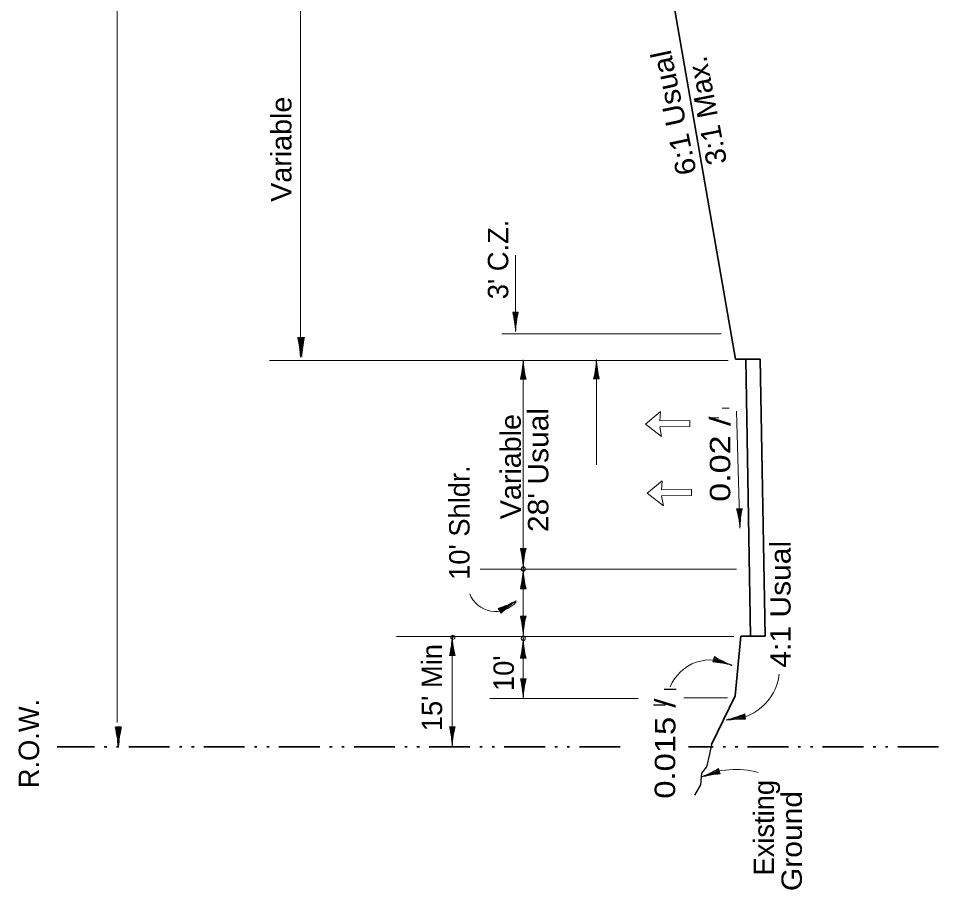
# Model space of a CAD drawing. Extents: x 2363427 to 2368559, y 6957299 to 6980140.
# Drawn here: x 2364644 to 2365275, y 6960219 to 6960816 of the extents above; entities that cross this region are included whole.
import ezdxf
from ezdxf.enums import TextEntityAlignment as Align

# ---------------------------------------------------------------- set-up
doc = ezdxf.new("R2010")
doc.units = 0
doc.header["$LTSCALE"] = 5.6
doc.header["$PDMODE"] = 32
doc.header["$PDSIZE"] = 2.8
doc.linetypes.add('DASH_DOUBLE_DOT', pattern=[9.2, 5, -1.2, 0.3, -1.2, 0.3, -1.2])
doc.linetypes.add('MEDIUM_DASHED', pattern=[4.5, 3, -1.5])
for name, color, linetype, lineweight in [('1', 7, 'Continuous', 13), ('3', 7, 'Continuous', 35), ('4', 7, 'Continuous', 13), ('40', 7, 'Continuous', 35), ('48', 7, 'Continuous', 25), ('8', 7, 'Continuous', 13)]:
    doc.layers.add(name, color=color, linetype=linetype, lineweight=lineweight)

msp = doc.modelspace()

# ---------------------------------------------------------------- linework, layer by layer
at = {"layer": '1'}
for p, q in [((2364983.119, 6960614.672), (2364986.949, 6960614.672)), ((2364983.119, 6960614.672), (2364986.949, 6960614.672)), ((2364983.469, 6960614.672), (2364983.469, 6960613.088)), ((2364983.469, 6960614.672), (2364983.469, 6960613.088)), ((2364983.969, 6960614.672), (2364983.969, 6960610.396)), ((2364983.969, 6960614.672), (2364983.969, 6960610.396)), ((2364984.469, 6960614.672), (2364984.469, 6960607.322)), ((2364984.469, 6960614.672), (2364984.469, 6960607.322)), ((2364984.969, 6960614.672), (2364984.969, 6960602.108)), ((2364984.969, 6960614.672), (2364984.969, 6960602.108)), ((2364985.469, 6960614.672), (2364985.469, 6960606.063)), ((2364985.469, 6960614.672), (2364985.469, 6960606.063)), ((2364985.969, 6960614.672), (2364985.969, 6960609.81)), ((2364985.969, 6960614.672), (2364985.969, 6960609.81)), ((2364986.469, 6960614.672), (2364986.469, 6960612.291)), ((2364986.469, 6960614.672), (2364986.469, 6960612.291))]:
    msp.add_line(p, q, dxfattribs=at)
at = {"layer": '1', "linetype": 'MEDIUM_DASHED', "lineweight": 25}
msp.add_lwpolyline([(2365119.393, 6960318.068), (2365118.041, 6960311.566), (2365116.013, 6960302.896), (2365112.633, 6960298.562), (2365111.957, 6960290.614), (2365107.901, 6960283.39)], dxfattribs=at)
at = {"layer": '1'}
for centre, start, end in [((2364912.912, 6960597.779), 2.84356, 13.52961), ((2364912.912, 6960597.779), 2.84356, 13.52961), ((2365057.159, 6960597.779), 166.47039, 177.15644), ((2365057.159, 6960597.779), 166.47039, 177.15644)]:
    msp.add_arc(centre, 72.212, start, end, dxfattribs=at)
at = {"layer": '3'}
for p, q in [((2365072.809, 6960945.418), (2365135.901, 6960582.428)), ((2365152.924, 6960582.429), (2365135.901, 6960582.428)), ((2365146.244, 6960392.394), (2365142.923, 6960582.429)), ((2365156.242, 6960392.503), (2365152.922, 6960582.516)), ((2365139.652, 6960392.365), (2365156.244, 6960392.437)), ((2365139.652, 6960392.365), (2365135.796, 6960351.6)), ((2365135.795, 6960351.601), (2365119.393, 6960318.069))]:
    msp.add_line(p, q, dxfattribs=at)
at = {"layer": '3', "linetype": 'DASH_DOUBLE_DOT'}
for p, q in [((2365056.852, 6960316.668), (2364670.615, 6960316.668)), ((2365275.227, 6960316.668), (2365103.646, 6960316.668))]:
    msp.add_line(p, q, dxfattribs=at)
at = {"layer": '4'}
for p, q in [((2364711.737, 6960333.27), (2364711.737, 6961383.778)), ((2364837.569, 6960593.58), (2364837.569, 6961228.746)), ((2364985.035, 6960601.361), (2364985.035, 6960653.723)), ((2364835.613, 6960597.226), (2364839.443, 6960597.226)), ((2364835.963, 6960597.226), (2364835.963, 6960595.64)), ((2364836.463, 6960597.226), (2364836.463, 6960592.949)), ((2364836.485, 6960597.226), (2364840.315, 6960597.226)), ((2364836.835, 6960597.226), (2364836.835, 6960595.64)), ((2364836.963, 6960597.226), (2364836.963, 6960589.876)), ((2364837.335, 6960597.226), (2364837.335, 6960592.949)), ((2364837.463, 6960597.226), (2364837.463, 6960584.662)), ((2364837.835, 6960597.226), (2364837.835, 6960589.876)), ((2364837.963, 6960597.226), (2364837.963, 6960588.616)), ((2364838.335, 6960597.226), (2364838.335, 6960584.662)), ((2364838.463, 6960597.226), (2364838.463, 6960592.364)), ((2364838.835, 6960597.226), (2364838.835, 6960588.616)), ((2364838.963, 6960597.226), (2364838.963, 6960594.844)), ((2364839.335, 6960597.226), (2364839.335, 6960592.364)), ((2364839.835, 6960597.226), (2364839.835, 6960594.844)), ((2365126.127, 6960599.72), (2364975.733, 6960599.72)), ((2364990.33, 6960582.06), (2364990.33, 6960349.827)), ((2365040.53, 6960582.3), (2365040.53, 6960510.039)), ((2365130.939, 6960581.552), (2364816.365, 6960581.552)), ((2364989.894, 6960568.748), (2364989.894, 6960577.358)), ((2364989.894, 6960568.748), (2364989.894, 6960577.358)), ((2364990.394, 6960568.748), (2364990.394, 6960581.312)), ((2364990.394, 6960568.748), (2364990.394, 6960581.312)), ((2364990.894, 6960568.748), (2364990.894, 6960576.098)), ((2364990.894, 6960568.748), (2364990.894, 6960576.098)), ((2365039.966, 6960568.989), (2365039.966, 6960576.339)), ((2365039.966, 6960568.989), (2365039.966, 6960576.339)), ((2365040.466, 6960568.989), (2365040.466, 6960581.553)), ((2365040.466, 6960568.989), (2365040.466, 6960581.553)), ((2365040.966, 6960568.989), (2365040.966, 6960577.598)), ((2365040.966, 6960568.989), (2365040.966, 6960577.598)), ((2364988.894, 6960568.748), (2364988.894, 6960571.13)), ((2364988.894, 6960568.748), (2364988.894, 6960571.13)), ((2364989.394, 6960568.748), (2364989.394, 6960573.61)), ((2364989.394, 6960568.748), (2364989.394, 6960573.61)), ((2364991.394, 6960568.748), (2364991.394, 6960573.025)), ((2364991.394, 6960568.748), (2364991.394, 6960573.025)), ((2364991.894, 6960568.748), (2364991.894, 6960570.334)), ((2364991.894, 6960568.748), (2364991.894, 6960570.334)), ((2365038.966, 6960568.989), (2365038.966, 6960570.573)), ((2365038.966, 6960568.989), (2365038.966, 6960570.573)), ((2365039.466, 6960568.989), (2365039.466, 6960573.265)), ((2365039.466, 6960568.989), (2365039.466, 6960573.265)), ((2365041.466, 6960568.989), (2365041.466, 6960573.851)), ((2365041.466, 6960568.989), (2365041.466, 6960573.851)), ((2365041.966, 6960568.989), (2365041.966, 6960571.37)), ((2365041.966, 6960568.989), (2365041.966, 6960571.37)), ((2364992.244, 6960568.748), (2364988.414, 6960568.748)), ((2364992.244, 6960568.748), (2364988.414, 6960568.748)), ((2365038.616, 6960568.989), (2365042.446, 6960568.989)), ((2365038.616, 6960568.989), (2365042.446, 6960568.989)), ((2365136.716, 6960546.874), (2365138.992, 6960466.62)), ((2365140.528, 6960479.981), (2365136.7, 6960479.872)), ((2365137.18, 6960479.886), (2365137.248, 6960477.506)), ((2365137.68, 6960479.9), (2365137.818, 6960475.04)), ((2365138.18, 6960479.914), (2365138.424, 6960471.308)), ((2365138.679, 6960479.928), (2365139.036, 6960467.37)), ((2365139.179, 6960479.942), (2365139.388, 6960472.596)), ((2365139.679, 6960479.957), (2365139.8, 6960475.682)), ((2365140.178, 6960479.971), (2365140.224, 6960478.386)), ((2364988.414, 6960452.662), (2364992.244, 6960452.662)), ((2364988.414, 6960452.662), (2364992.244, 6960452.662)), ((2364988.764, 6960452.662), (2364988.764, 6960451.078)), ((2364988.764, 6960452.662), (2364988.764, 6960451.078)), ((2364989.264, 6960452.662), (2364989.264, 6960448.386)), ((2364989.264, 6960452.662), (2364989.264, 6960448.386)), ((2364989.764, 6960452.662), (2364989.764, 6960445.312)), ((2364989.764, 6960452.662), (2364989.764, 6960445.312)), ((2364990.264, 6960452.662), (2364990.264, 6960440.098)), ((2364990.264, 6960452.662), (2364990.264, 6960440.098)), ((2364990.764, 6960452.662), (2364990.764, 6960444.053)), ((2364990.764, 6960452.662), (2364990.764, 6960444.053)), ((2364991.264, 6960452.662), (2364991.264, 6960447.8)), ((2364991.264, 6960452.662), (2364991.264, 6960447.8)), ((2364991.764, 6960452.662), (2364991.764, 6960450.281)), ((2364991.764, 6960452.662), (2364991.764, 6960450.281)), ((2365136.677, 6960438.365), (2364960.809, 6960438.365)), ((2364990.394, 6960425.013), (2364990.394, 6960437.577)), ((2364990.394, 6960425.013), (2364990.394, 6960437.577)), ((2364989.894, 6960425.013), (2364989.894, 6960433.623)), ((2364989.894, 6960425.013), (2364989.894, 6960433.623)), ((2364990.894, 6960425.013), (2364990.894, 6960432.363)), ((2364990.894, 6960425.013), (2364990.894, 6960432.363)), ((2364992.244, 6960425.013), (2364988.414, 6960425.013)), ((2364992.244, 6960425.013), (2364988.414, 6960425.013)), ((2364988.894, 6960425.013), (2364988.894, 6960427.395)), ((2364988.894, 6960425.013), (2364988.894, 6960427.395)), ((2364989.394, 6960425.013), (2364989.394, 6960429.875)), ((2364989.394, 6960425.013), (2364989.394, 6960429.875)), ((2364991.394, 6960425.013), (2364991.394, 6960429.29)), ((2364991.394, 6960425.013), (2364991.394, 6960429.29)), ((2364991.894, 6960425.013), (2364991.894, 6960426.599)), ((2364991.894, 6960425.013), (2364991.894, 6960426.599)), ((2364975.192, 6960408.208), (2364973.204, 6960411.482)), ((2364973.454, 6960411.071), (2364975.489, 6960412.307)), ((2364973.713, 6960410.645), (2364977.869, 6960413.167)), ((2364973.972, 6960410.217), (2364981.332, 6960414.685)), ((2364974.232, 6960409.789), (2364984.972, 6960416.309)), ((2364974.491, 6960409.362), (2364980.774, 6960413.176)), ((2364974.75, 6960408.935), (2364978.406, 6960411.153)), ((2364975.01, 6960408.507), (2364976.365, 6960409.33)), ((2364988.414, 6960406.184), (2364992.244, 6960406.184)), ((2364988.414, 6960406.184), (2364992.244, 6960406.184)), ((2364988.764, 6960406.184), (2364988.764, 6960404.6)), ((2364988.764, 6960406.184), (2364988.764, 6960404.6)), ((2364989.264, 6960406.184), (2364989.264, 6960401.908)), ((2364989.264, 6960406.184), (2364989.264, 6960401.908)), ((2364989.764, 6960406.184), (2364989.764, 6960398.834)), ((2364989.764, 6960406.184), (2364989.764, 6960398.834)), ((2364990.264, 6960406.184), (2364990.264, 6960393.62)), ((2364990.264, 6960406.184), (2364990.264, 6960393.62)), ((2364990.764, 6960406.184), (2364990.764, 6960397.575)), ((2364990.764, 6960406.184), (2364990.764, 6960397.575)), ((2364991.264, 6960406.184), (2364991.264, 6960401.322)), ((2364991.264, 6960406.184), (2364991.264, 6960401.322)), ((2364991.764, 6960406.184), (2364991.764, 6960403.803)), ((2364991.764, 6960406.184), (2364991.764, 6960403.803)), ((2364941.663, 6960392.504), (2364941.663, 6960316.968)), ((2365134.747, 6960392.301), (2364903.418, 6960392.301)), ((2364941.099, 6960379.192), (2364941.099, 6960386.542)), ((2364941.099, 6960379.192), (2364941.099, 6960386.542)), ((2364941.599, 6960379.192), (2364941.599, 6960391.756)), ((2364941.599, 6960379.192), (2364941.599, 6960391.756)), ((2364942.099, 6960379.192), (2364942.099, 6960387.802)), ((2364942.099, 6960379.192), (2364942.099, 6960387.802)), ((2364990.394, 6960377.417), (2364990.394, 6960389.981)), ((2364990.394, 6960377.417), (2364990.394, 6960389.981)), ((2364940.099, 6960379.192), (2364940.099, 6960380.777)), ((2364940.099, 6960379.192), (2364940.099, 6960380.777)), ((2364940.599, 6960379.192), (2364940.599, 6960383.468)), ((2364940.599, 6960379.192), (2364940.599, 6960383.468)), ((2364942.599, 6960379.192), (2364942.599, 6960384.054)), ((2364942.599, 6960379.192), (2364942.599, 6960384.054)), ((2364943.099, 6960379.192), (2364943.099, 6960381.574)), ((2364943.099, 6960379.192), (2364943.099, 6960381.574)), ((2364988.894, 6960377.417), (2364988.894, 6960379.799)), ((2364988.894, 6960377.417), (2364988.894, 6960379.799)), ((2364989.394, 6960377.417), (2364989.394, 6960382.279)), ((2364989.394, 6960377.417), (2364989.394, 6960382.279)), ((2364989.894, 6960377.417), (2364989.894, 6960386.027)), ((2364989.894, 6960377.417), (2364989.894, 6960386.027)), ((2364990.894, 6960377.417), (2364990.894, 6960384.767)), ((2364990.894, 6960377.417), (2364990.894, 6960384.767)), ((2364991.394, 6960377.417), (2364991.394, 6960381.694)), ((2364991.394, 6960377.417), (2364991.394, 6960381.694)), ((2364939.749, 6960379.192), (2364943.579, 6960379.192)), ((2364939.749, 6960379.192), (2364943.579, 6960379.192)), ((2364992.244, 6960377.417), (2364988.414, 6960377.417)), ((2364992.244, 6960377.417), (2364988.414, 6960377.417)), ((2364991.894, 6960377.417), (2364991.894, 6960379.003)), ((2364991.894, 6960377.417), (2364991.894, 6960379.003)), ((2365120.273, 6960374.788), (2365121.438, 6960378.437)), ((2365120.38, 6960375.121), (2365121.89, 6960374.639)), ((2365120.532, 6960375.598), (2365124.606, 6960374.297)), ((2365120.684, 6960376.074), (2365127.685, 6960373.837)), ((2365120.836, 6960376.551), (2365132.804, 6960372.727)), ((2365120.988, 6960377.027), (2365129.19, 6960374.407)), ((2365121.14, 6960377.503), (2365125.772, 6960376.023)), ((2365121.292, 6960377.979), (2365123.561, 6960377.255)), ((2364988.435, 6960363.224), (2364992.265, 6960363.224)), ((2364988.435, 6960363.224), (2364992.265, 6960363.224)), ((2364988.785, 6960363.224), (2364988.785, 6960361.64)), ((2364988.785, 6960363.224), (2364988.785, 6960361.64)), ((2364989.285, 6960363.224), (2364989.285, 6960358.948)), ((2364989.285, 6960363.224), (2364989.285, 6960358.948)), ((2364989.785, 6960363.224), (2364989.785, 6960355.874)), ((2364989.785, 6960363.224), (2364989.785, 6960355.874)), ((2364990.285, 6960363.224), (2364990.285, 6960350.66)), ((2364990.285, 6960363.224), (2364990.285, 6960350.66)), ((2364990.785, 6960363.224), (2364990.785, 6960354.615)), ((2364990.785, 6960363.224), (2364990.785, 6960354.615)), ((2364991.285, 6960363.224), (2364991.285, 6960358.362)), ((2364991.285, 6960363.224), (2364991.285, 6960358.362)), ((2364991.785, 6960363.224), (2364991.785, 6960360.843)), ((2364991.785, 6960363.224), (2364991.785, 6960360.843)), ((2365069.268, 6960349.827), (2364967.392, 6960349.827)), ((2365130.5, 6960350.216), (2365100.425, 6960350.216)), ((2365142.573, 6960337.281), (2365130.197, 6960335.116)), ((2365142.487, 6960337.775), (2365134.007, 6960336.291)), ((2365142.66, 6960336.789), (2365135.419, 6960335.522)), ((2365142.401, 6960338.267), (2365137.611, 6960337.429)), ((2365142.746, 6960336.297), (2365138.533, 6960335.559)), ((2365142.315, 6960338.759), (2365139.969, 6960338.349)), ((2365142.832, 6960335.805), (2365141.271, 6960335.531)), ((2365142.893, 6960335.46), (2365142.233, 6960339.232)), ((2364943.579, 6960330.28), (2364939.749, 6960330.28)), ((2364943.579, 6960330.28), (2364939.749, 6960330.28)), ((2364940.229, 6960330.28), (2364940.229, 6960327.898)), ((2364940.229, 6960330.28), (2364940.229, 6960327.898)), ((2364940.729, 6960330.28), (2364940.729, 6960325.418)), ((2364940.729, 6960330.28), (2364940.729, 6960325.418)), ((2364941.229, 6960330.28), (2364941.229, 6960321.67)), ((2364941.229, 6960330.28), (2364941.229, 6960321.67)), ((2364941.729, 6960330.28), (2364941.729, 6960317.716)), ((2364941.729, 6960330.28), (2364941.729, 6960317.716)), ((2364942.229, 6960330.28), (2364942.229, 6960322.93)), ((2364942.229, 6960330.28), (2364942.229, 6960322.93)), ((2364942.729, 6960330.28), (2364942.729, 6960326.004)), ((2364942.729, 6960330.28), (2364942.729, 6960326.004)), ((2364943.229, 6960330.28), (2364943.229, 6960328.695)), ((2364943.229, 6960330.28), (2364943.229, 6960328.695)), ((2365124.851, 6960299.936), (2365112.906, 6960296.042)), ((2365125.006, 6960299.461), (2365116.82, 6960296.793)), ((2365124.696, 6960300.411), (2365117.708, 6960298.133)), ((2365124.541, 6960300.887), (2365120.475, 6960299.561)), ((2365125.161, 6960298.985), (2365120.538, 6960297.479)), ((2365124.386, 6960301.363), (2365122.879, 6960300.871)), ((2365125.316, 6960298.51), (2365123.052, 6960297.772)), ((2365124.278, 6960301.695), (2365125.464, 6960298.053))]:
    msp.add_line(p, q, dxfattribs=at)
at = {"layer": '4', "lineweight": 25}
for p, q in [((2365095.261, 6960355.863), (2365087.1, 6960355.863)), ((2365087.943, 6960345.039), (2365079.782, 6960345.039))]:
    msp.add_line(p, q, dxfattribs=at)
at = {"layer": '4', "lineweight": 35}
for p, q in [((2364710.679, 6960329.98), (2364714.509, 6960329.98)), ((2364711.029, 6960329.98), (2364711.029, 6960328.395)), ((2364711.529, 6960329.98), (2364711.529, 6960325.704)), ((2364712.029, 6960329.98), (2364712.029, 6960322.63)), ((2364712.529, 6960329.98), (2364712.529, 6960317.416)), ((2364713.029, 6960329.98), (2364713.029, 6960321.37)), ((2364713.529, 6960329.98), (2364713.529, 6960325.118)), ((2364714.029, 6960329.98), (2364714.029, 6960327.598))]:
    msp.add_line(p, q, dxfattribs=at)
at = {"layer": '4'}
for centre, radius, start, end in [((2364765.404, 6960580.332), 72.212, 2.84356, 13.52961), ((2364766.277, 6960580.332), 72.212, 2.84356, 13.52961), ((2364909.651, 6960580.332), 72.212, 166.47039, 177.15644), ((2364910.524, 6960580.332), 72.212, 166.47039, 177.15644), ((2364918.205, 6960585.642), 72.212, 346.47039, 357.15644), ((2364918.205, 6960585.642), 72.212, 346.47039, 357.15644), ((2365062.452, 6960585.642), 72.212, 182.84356, 193.52961), ((2365062.452, 6960585.642), 72.212, 182.84356, 193.52961), ((2364968.406, 6960585.883), 72.212, 346.47039, 357.15644), ((2364968.406, 6960585.883), 72.212, 346.47039, 357.15644), ((2365112.653, 6960585.883), 72.212, 182.84356, 193.52961), ((2365112.653, 6960585.883), 72.212, 182.84356, 193.52961), ((2365066.997, 6960460.996), 72.212, 4.46769, 15.15374), ((2365211.186, 6960465.084), 72.212, 168.09453, 178.78057), ((2364918.205, 6960435.768), 72.212, 2.84356, 13.52961), ((2364918.205, 6960435.768), 72.212, 2.84356, 13.52961), ((2365062.452, 6960435.768), 72.212, 166.47039, 177.15644), ((2365062.452, 6960435.768), 72.212, 166.47039, 177.15644), ((2364918.205, 6960441.907), 72.212, 346.47039, 357.15644), ((2364918.205, 6960441.907), 72.212, 346.47039, 357.15644), ((2365062.452, 6960441.907), 72.212, 182.84356, 193.52961), ((2365062.452, 6960441.907), 72.212, 182.84356, 193.52961), ((2364971.198, 6960428.21), 18.823, 200.84978, 319.74384), ((2364951.212, 6960480.264), 72.212, 287.73061, 298.41666), ((2365026.066, 6960356.959), 72.212, 124.10378, 134.78983), ((2364918.205, 6960389.291), 72.212, 2.84356, 13.52961), ((2364918.205, 6960389.291), 72.212, 2.84356, 13.52961), ((2365062.452, 6960389.291), 72.212, 166.47039, 177.15644), ((2365062.452, 6960389.291), 72.212, 166.47039, 177.15644), ((2364869.539, 6960396.086), 72.212, 346.47039, 357.15644), ((2364869.539, 6960396.086), 72.212, 346.47039, 357.15644), ((2365013.786, 6960396.086), 72.212, 182.84356, 193.52961), ((2365013.786, 6960396.086), 72.212, 182.84356, 193.52961), ((2364918.205, 6960394.311), 72.212, 346.47039, 357.15644), ((2364918.205, 6960394.311), 72.212, 346.47039, 357.15644), ((2365062.452, 6960394.311), 72.212, 182.84356, 193.52961), ((2365062.452, 6960394.311), 72.212, 182.84356, 193.52961), ((2365118.516, 6960346.499), 29.635, 59.62074, 157.81619), ((2365115, 6960302.768), 72.212, 75.12659, 85.81264), ((2365158.896, 6960440.174), 72.212, 238.75343, 249.43948), ((2364918.227, 6960346.331), 72.212, 2.84356, 13.52961), ((2364918.227, 6960346.331), 72.212, 2.84356, 13.52961), ((2365062.474, 6960346.331), 72.212, 166.47039, 177.15644), ((2365062.474, 6960346.331), 72.212, 166.47039, 177.15644), ((2365130.247, 6960370.955), 36.023, 268.88537, 352.71261), ((2365113.488, 6960405.478), 72.212, 282.77005, 293.4561), ((2365138.354, 6960263.39), 72.212, 86.39688, 97.08293), ((2364869.539, 6960313.387), 72.212, 2.84356, 13.52961), ((2364869.539, 6960313.387), 72.212, 2.84356, 13.52961), ((2365013.786, 6960313.387), 72.212, 166.47039, 177.15644), ((2365013.786, 6960313.387), 72.212, 166.47039, 177.15644), ((2365136.116, 6960244.248), 56.809, 74.22951, 114.90949), ((2365086.455, 6960363.21), 72.212, 290.89929, 301.58534), ((2365131.163, 6960226.067), 72.212, 94.52612, 105.21217)]:
    msp.add_arc(centre, radius, start, end, dxfattribs=at)
at = {"layer": '4', "lineweight": 35}
for centre, start, end in [((2364640.471, 6960313.087), 2.84356, 13.52961), ((2364784.718, 6960313.087), 166.47039, 177.15644)]:
    msp.add_arc(centre, 72.212, start, end, dxfattribs=at)
at = {"layer": '4'}
for p in [(2364990.33, 6960451.147), (2364990.33, 6960438.726), (2364990.33, 6960438.325), (2364942.061, 6960391.605), (2364990.33, 6960391.13), (2364990.33, 6960390.729)]:
    msp.add_point(p, dxfattribs=at)
at = {"layer": '40', "lineweight": 13}
for p, q in [((2365084.003, 6960540.158), (2365104.508, 6960540.353)), ((2365085.188, 6960492.765), (2365105.694, 6960492.96))]:
    msp.add_line(p, q, dxfattribs=at)
for points in [[(2365084.003, 6960540.158), (2365084.536, 6960546.473), (2365074.148, 6960537.938), (2365085.248, 6960529.335), (2365084.04, 6960536.063)], [(2365084.04, 6960536.063), (2365104.546, 6960536.258), (2365104.508, 6960540.353)], [(2365085.188, 6960492.765), (2365085.721, 6960499.08), (2365075.334, 6960490.545), (2365086.434, 6960481.943), (2365085.226, 6960488.67)], [(2365085.226, 6960488.67), (2365105.731, 6960488.865), (2365105.694, 6960492.96)]]:
    msp.add_lwpolyline(points, dxfattribs=at)
at = {"layer": '48', "lineweight": 13}
for p, q in [((2365126.869, 6960548.76), (2365131.639, 6960548.76)), ((2365124.6, 6960542.263), (2365118.876, 6960542.263))]:
    msp.add_line(p, q, dxfattribs=at)
msp.add_lwpolyline([(2365146.244, 6960392.394), (2365156.242, 6960392.503), (2365152.922, 6960582.516), (2365142.923, 6960582.429)], close=True, dxfattribs=at)
at = {"layer": '8'}
for points in [[(2365074.148, 6960537.938), (2365084.536, 6960546.473), (2365084.003, 6960540.158), (2365104.508, 6960540.353), (2365104.546, 6960536.258), (2365084.04, 6960536.063), (2365085.248, 6960529.335)], [(2365075.334, 6960490.545), (2365085.721, 6960499.08), (2365085.188, 6960492.765), (2365105.694, 6960492.96), (2365105.731, 6960488.865), (2365085.226, 6960488.67), (2365086.434, 6960481.943)]]:
    msp.add_lwpolyline(points, close=True, dxfattribs=at)

# ---------------------------------------------------------------- texts
at = {"layer": '1', "width": 1.05}
msp.add_text('Variable', height=14, rotation=90, dxfattribs=at).set_placement((2364831.367, 6960726.418), align=Align.CENTER)
at = {"layer": '4'}
for s, rotation, width, p in [('6:1 Usual', 101.975, 1.1, (2365100.367, 6960752.839)), ('3:1 Max.', 100.991, 1.05, (2365123.013, 6960754.196)), ('Variable', 90, 1.05, (2364988.69, 6960508.747)), ("28' Usual", 90, 1.1, (2365007.531, 6960506.441)), ('0.02 /', 90, 1.25, (2365132.335, 6960513.872)), ('4:1 Usual', 90.006, 1.1, (2365173.703, 6960414.348)), ('0.015 /', 89.708, 1.2, (2365094.621, 6960315.293)), ('Ground', 90, 1.1, (2365181.451, 6960251.963))]:
    msp.add_text(s, height=14, rotation=rotation, dxfattribs=dict(at, width=width)).set_placement(p, align=Align.CENTER)
for s, p in [("3' C.Z.", (2364980.051, 6960650.821)), ("10' Shldr.", (2364953.516, 6960470.349)), ("15' Min", (2364934.694, 6960357.172)), ("10' ", (2364983.898, 6960369.629)), ('R.O.W.', (2364658.273, 6960318.833)), ('Existing ', (2365162.36, 6960263.685))]:
    msp.add_text(s, height=14, rotation=90, dxfattribs=at).set_placement(p, align=Align.CENTER)

doc.saveas('drawing.dxf')
